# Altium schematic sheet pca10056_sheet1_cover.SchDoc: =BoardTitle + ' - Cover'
size A3; Organization: Nordic Semiconductor; DocumentNumber: 1; SheetNumber: 1; SheetTotal: 6; CompanyName: Nordic Semiconductor; DocumentSize: A3
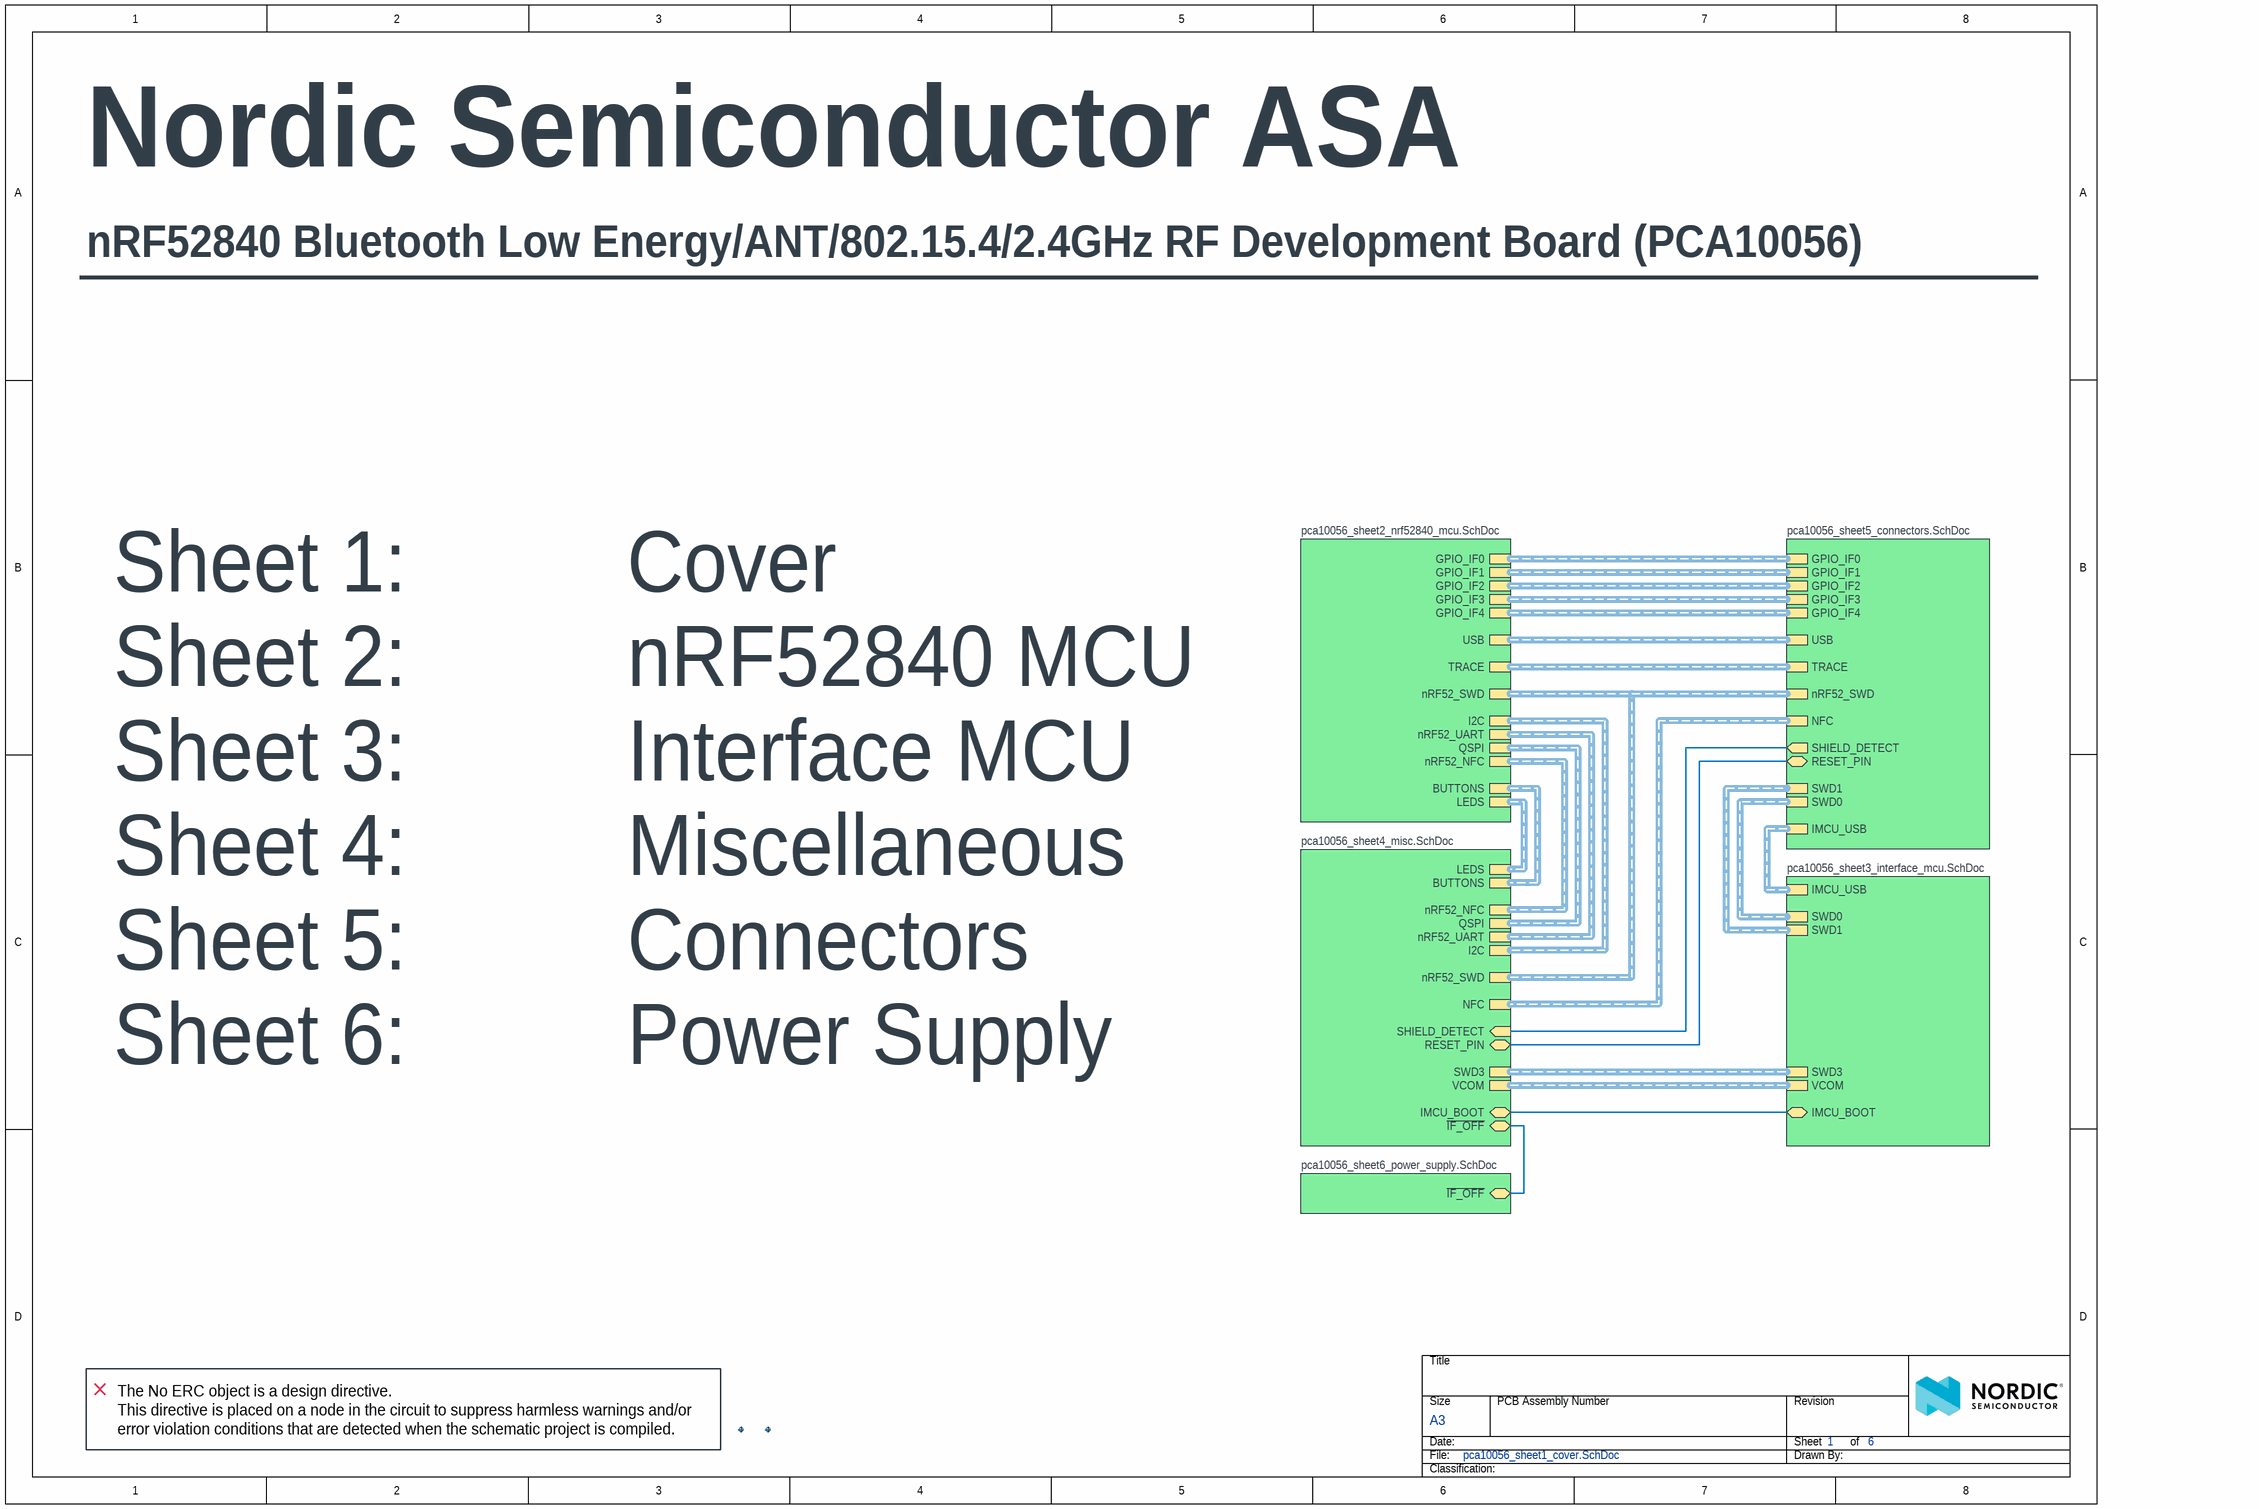
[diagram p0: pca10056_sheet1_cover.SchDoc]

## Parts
Fid1  Fiducial mark  [Fiducial]  (value not drawn)
Fid2  Fiducial mark  [Fiducial]  (value not drawn)

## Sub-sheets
? = pca10056_sheet2_nrf52840_mcu.SchDoc: nRF52_SWD (harness SWD), BUTTONS (harness BUTTONS), GPIO_IF2 (harness GPIO_IF2), GPIO_IF4 (harness GPIO_IF4), I2C (harness I2C), nRF52_UART (harness nRF52_UART), GPIO_IF1 (harness GPIO_IF1), GPIO_IF0 (harness GPIO_IF0), QSPI (harness QSPI), TRACE (harness TRACE), nRF52_NFC (harness NFC), LEDS (harness LED), USB (harness USB), GPIO_IF3 (harness GPIO_IF3)
? = pca10056_sheet3_interface_mcu.SchDoc: SWD0 (harness SWD), IMCU_BOOT (bidir), SWD3 (harness SWD), SWD1 (harness SWD), VCOM (harness UART), IMCU_USB (harness USB)
? = pca10056_sheet4_misc.SchDoc: NFC (harness NFC), QSPI (harness QSPI), SHIELD_DETECT (in), LEDS (harness LED), SWD3 (harness SWD), nRF52_UART (harness nRF52_UART), ~{IF_OFF} (bidir), nRF52_NFC (harness NFC), I2C (harness I2C), BUTTONS (harness BUTTONS), IMCU_BOOT (bidir), RESET_PIN (bidir), nRF52_SWD (harness SWD), VCOM (harness UART)
? = pca10056_sheet5_connectors.SchDoc: SWD0 (harness SWD), SHIELD_DETECT (out), SWD1 (harness SWD), RESET_PIN (bidir), GPIO_IF2 (harness GPIO_IF2), USB (harness USB), GPIO_IF4 (harness GPIO_IF4), nRF52_SWD (harness SWD), GPIO_IF3 (harness GPIO_IF3), TRACE (harness TRACE), GPIO_IF1 (harness GPIO_IF1), GPIO_IF0 (harness GPIO_IF0), IMCU_USB (harness USB), NFC (harness NFC)
? = pca10056_sheet6_power_supply.SchDoc: ~{IF_OFF} (bidir)

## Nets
(unnamed): sheet /IMCU_BOOT, sheet /IMCU_BOOT
(unnamed): sheet /SHIELD_DETECT, sheet /SHIELD_DETECT  [a separate net that carries the same name]
(unnamed): sheet /~{IF_OFF}, sheet /~{IF_OFF}  [a separate net that carries the same name]
(unnamed): sheet /RESET_PIN, sheet /RESET_PIN  [a separate net that carries the same name]

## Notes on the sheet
- Nordic Semiconductor ASA
- ________________________________________________________________
- nRF52840 Bluetooth Low Energy/ANT/802.15.4/2.4GHz RF Development Board (PCA10056)
- Sheet 1:          Cover
- Sheet 2:          nRF52840 MCU
- Sheet 3:          Interface MCU
- Sheet 4:          Miscellaneous
- Sheet 5:          Connectors
- Sheet 6:          Power Supply
- (near Fid1) The No ERC object is a design directive.
  This directive is placed on a node in the circuit to suppress harmless warnings and/or error violation conditions that are detected when the schematic project is compiled.

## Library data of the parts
Fid1 Fid2 = Fid-Mark: Manufacturer: N.A.; Part number NEMS: 100500073; Value: N.A.; Pad Count: 1; Component Status: Active; System: Connector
